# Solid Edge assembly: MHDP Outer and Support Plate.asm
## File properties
Author: davee
Template: Normal.asm
Last saved by: davee
Revision: 3
Application: Solid Edge
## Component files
MH Die Plate Outer.par
Support Plate.par
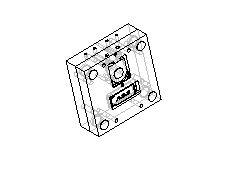
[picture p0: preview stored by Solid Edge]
